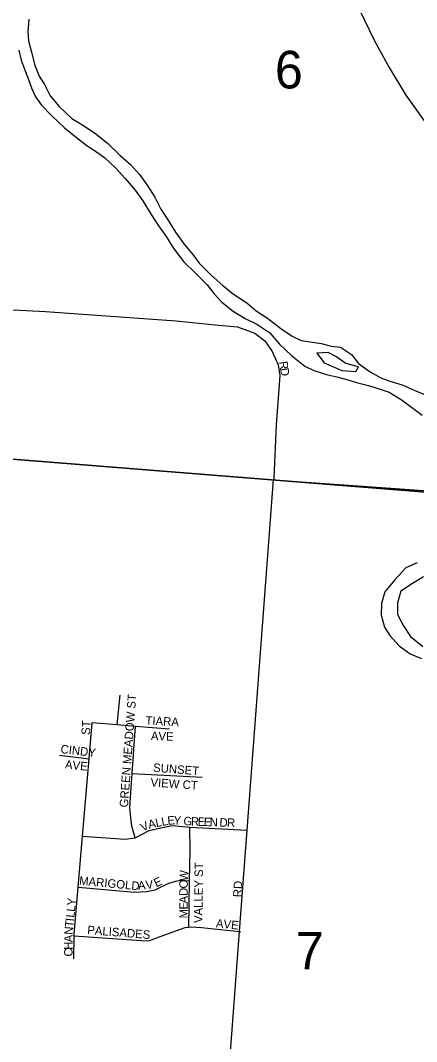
# Model space of a CAD drawing. Extents: x 0 to 34, y 0 to 22.
# Drawn here: x 4.316 to 4.758, y 16.625 to 17.763 of the extents above; entities that cross this region are included whole.
import ezdxf

# ---------------------------------------------------------------- set-up
doc = ezdxf.new("R2010")
doc.units = 0
for name, color, linetype in [('GM_X_City_Street', 7, 'Continuous'), ('GM_X_City_Street_Text', 7, 'Continuous'), ('GM_X_Major_River', 7, 'Continuous'), ('GM_X_Section', 7, 'Continuous'), ('GM_X_Section_Text', 7, 'Continuous'), ('GM_X_US_Route', 7, 'Continuous')]:
    doc.layers.add(name, color=color, linetype=linetype)

msp = doc.modelspace()

# ---------------------------------------------------------------- linework, layer by layer
at = {"layer": 'GM_X_City_Street'}
for points in [[(4.1861, 17.4467), (4.3444, 17.4382), (4.49, 17.4278), (4.5336, 17.4235), (4.5584, 17.4213), (4.5777, 17.4143), (4.589, 17.4057), (4.5971, 17.3939), (4.6036, 17.3788), (4.6057, 17.3669), (4.6014, 17.312), (4.5988, 17.2527)], [(4.5216, 16.2252), (4.5608, 16.7472), (4.5693, 16.8602), (4.5987, 17.2509)], [(4.5988, 17.2527), (4.5987, 17.2509), (4.8338, 17.234), (4.9075, 17.2287), (5.0472, 17.218), (5.1112, 17.2137), (5.1718, 17.2206), (5.2384, 17.2265), (5.2646, 17.2259), (5.2903, 17.2238), (5.3134, 17.2192), (5.3431, 17.2104), (5.3688, 17.2001), (5.3842, 17.1924), (5.3949, 17.1868), (5.44, 17.1631), (5.4728, 17.1515), (5.4951, 17.1479), (5.5183, 17.1487), (5.5352, 17.1515), (5.5507, 17.1555), (5.565, 17.1611), (5.578, 17.1683), (5.5851, 17.1734)], [(4.4243, 16.9779), (4.4276, 17.0106)], [(4.3759, 16.7167), (4.3761, 16.7426), (4.3761, 16.7445), (4.3806, 16.7966), (4.3856, 16.8535), (4.393, 16.9398), (4.3965, 16.9801)], [(4.3965, 16.9801), (4.4243, 16.9779), (4.4448, 16.9762), (4.4824, 16.9732)], [(4.4443, 16.8518), (4.4406, 16.8647), (4.4395, 16.8742), (4.4383, 16.8856), (4.4397, 16.9077), (4.4409, 16.9233), (4.4448, 16.9762)], [(4.3598, 16.9439), (4.393, 16.9398)], [(4.4409, 16.9233), (4.519, 16.9193)], [(4.3856, 16.8535), (4.4327, 16.8503), (4.4443, 16.8518), (4.46, 16.8599), (4.4729, 16.863), (4.4854, 16.8653), (4.5053, 16.8636), (4.5693, 16.8602)], [(4.504, 16.7522), (4.505, 16.8038), (4.5057, 16.8376), (4.5053, 16.8636)], [(4.3806, 16.7966), (4.4436, 16.7911), (4.4569, 16.7919), (4.4667, 16.7938), (4.4819, 16.8011), (4.491, 16.8037), (4.4955, 16.8045), (4.505, 16.8038)], [(4.3761, 16.7426), (4.4567, 16.7368), (4.4608, 16.7372), (4.4722, 16.7418), (4.4999, 16.7517), (4.504, 16.7522), (4.5067, 16.7525), (4.5181, 16.7518), (4.5608, 16.7472), (4.562, 16.7471)]]:
    msp.add_lwpolyline(points, dxfattribs=at)
at = {"layer": 'GM_X_Major_River'}
for points in [[(4.3257, 17.7641), (4.3245, 17.7501), (4.3253, 17.7402), (4.3287, 17.7273), (4.3325, 17.7129), (4.3374, 17.7008), (4.3431, 17.6913), (4.3495, 17.6788), (4.3594, 17.6667), (4.3737, 17.6534), (4.3866, 17.6458), (4.4006, 17.6363), (4.4139, 17.6257), (4.4271, 17.6128), (4.4392, 17.6022), (4.4491, 17.5909), (4.4578, 17.5791), (4.4661, 17.5658), (4.4729, 17.5526), (4.4813, 17.5393), (4.4892, 17.5268), (4.4987, 17.5139), (4.5085, 17.5018), (4.5157, 17.4923), (4.529, 17.479), (4.5422, 17.4673), (4.5539, 17.4578)], [(4.3147, 17.7296), (4.3173, 17.7186)], [(4.3173, 17.7186), (4.3215, 17.7068), (4.3253, 17.697), (4.3287, 17.6875), (4.3332, 17.6776), (4.3397, 17.6682), (4.3514, 17.6564), (4.3654, 17.6431), (4.3787, 17.6325), (4.3904, 17.6234), (4.4002, 17.617), (4.4101, 17.6102), (4.4226, 17.598), (4.4332, 17.5867), (4.4442, 17.5738), (4.4529, 17.5617), (4.462, 17.5465), (4.4703, 17.534), (4.479, 17.5218), (4.4866, 17.5093), (4.4983, 17.4942), (4.5119, 17.4809), (4.5244, 17.468), (4.5324, 17.4582), (4.5411, 17.4487), (4.5536, 17.4388), (4.5668, 17.4305), (4.5801, 17.4244), (4.5945, 17.4146), (4.6054, 17.4021), (4.6187, 17.3892), (4.6335, 17.3774), (4.6437, 17.3725), (4.6577, 17.3683), (4.6706, 17.3653), (4.6804, 17.3627), (4.691, 17.3593), (4.7043, 17.3559), (4.7175, 17.3517), (4.7277, 17.3483), (4.741, 17.3403), (4.7539, 17.3305), (4.7645, 17.3229)], [(4.5539, 17.4578), (4.5687, 17.4479), (4.5793, 17.4392), (4.5918, 17.4309), (4.6066, 17.4195), (4.6194, 17.4108), (4.6293, 17.4059), (4.6395, 17.4044), (4.652, 17.4029), (4.663, 17.3998), (4.6732, 17.3987), (4.6857, 17.3904), (4.6933, 17.3805), (4.7062, 17.371), (4.7183, 17.3646), (4.7281, 17.3608), (4.7421, 17.3566), (4.7554, 17.3506), (4.7671, 17.346)], [(4.6933, 17.3767), (4.6793, 17.3805), (4.6679, 17.3881), (4.6596, 17.3926), (4.6467, 17.3918)], [(4.6467, 17.3918), (4.655, 17.3812), (4.6747, 17.3725), (4.6902, 17.3714), (4.6933, 17.3767)], [(4.7587, 17.1583), (4.7462, 17.1526), (4.7337, 17.1393), (4.7228, 17.126), (4.719, 17.1131), (4.7186, 17.0999), (4.7224, 17.0866), (4.7284, 17.0771), (4.7387, 17.0658), (4.7511, 17.0567), (4.7636, 17.0517)], [(4.7659, 17.1428), (4.7534, 17.1352), (4.7406, 17.1268), (4.7368, 17.1135), (4.7368, 17.1006), (4.7436, 17.0881), (4.7515, 17.076), (4.7652, 17.065)]]:
    msp.add_lwpolyline(points, dxfattribs=at)
at = {"layer": 'GM_X_Section'}
for points in [[(4.2418, 18.2267), (4.7469, 18.1907), (5.1885, 18.1592), (5.123, 17.2087), (4.1767, 17.2841)], [(4.1767, 17.2841), (5.123, 17.2087), (5.0408, 16.1927), (4.1066, 16.2613), (4.1718, 17.2163)]]:
    msp.add_lwpolyline(points, close=True, dxfattribs=at)
at = {"layer": 'GM_X_US_Route'}
msp.add_lwpolyline([(4.6943, 17.7748), (4.7113, 17.7399), (4.7276, 17.7105), (4.7461, 17.6796), (4.7741, 17.6405), (4.8111, 17.5941), (4.8412, 17.5624), (4.8703, 17.5346), (4.9071, 17.5032), (4.9636, 17.4629), (5.0105, 17.4353), (5.0559, 17.4124), (5.093, 17.397), (5.1381, 17.3797), (5.3028, 17.3197), (5.444, 17.2679), (5.578, 17.2191), (5.6056, 17.2084)], dxfattribs=at)

# ---------------------------------------------------------------- texts
at = {"layer": 'GM_X_City_Street_Text'}
for s, rotation, p in [('R', 278.8994, (4.6047, 17.3822)), ('D', 278.226, (4.6059, 17.3748)), ('GREEN MEADOW ST', 85.7318, (4.4362, 16.8853)), ('ST', 86.4254, (4.3937, 16.9662)), ('TIARA', 357.27, (4.4556, 16.9779)), ('AVE', 358.0261, (4.4617, 16.9607)), ('CINDY', 353.5154, (4.3607, 16.9462)), ('AVE', 354.0969, (4.3657, 16.9291)), ('SUNSET', 355.5994, (4.464, 16.9254)), ('VIEW CT', 355.9842, (4.4611, 16.9091)), ('V', 25.0988, (4.4528, 16.8584)), ('A', 13.4107, (4.4598, 16.8617)), ('L', 10.6885, (4.4678, 16.8636)), ('L', 10.7131, (4.4744, 16.8649)), ('E', 5.3626, (4.4807, 16.8661)), ('Y', 356.6977, (4.4869, 16.8667)), ('G', 355.8157, (4.4978, 16.866)), ('R', 357.7837, (4.5064, 16.8654)), ('E', 358.2096, (4.514, 16.8651)), ('E', 358.1964, (4.5207, 16.8649)), ('N', 358.2026, (4.5273, 16.8647)), ('D', 358.2074, (4.5382, 16.8643)), ('R', 358.188, (4.5465, 16.8641)), ('VALLEY ST', 89.2365, (4.5192, 16.7567)), ('W', 86.5013, (4.503, 16.8034)), ('MARIGOLD', 354.6676, (4.3815, 16.7995)), ('A', 5.5388, (4.4478, 16.7937)), ('V', 7.8839, (4.4566, 16.7945)), ('E', 24.5582, (4.4677, 16.7965)), ('O', 89.4316, (4.5029, 16.7952)), ('RD', 86.9884, (4.5629, 16.7853)), ('D', 89.9703, (4.5029, 16.7869)), ('Y', 84.1763, (4.3777, 16.7757)), ('A', 89.9703, (4.5029, 16.7786)), ('E', 89.9707, (4.5029, 16.7719)), ('L', 84.173, (4.3764, 16.7624)), ('L', 84.1977, (4.377, 16.769)), ('M', 89.9636, (4.5029, 16.7619)), ('T', 84.2269, (4.3753, 16.7516)), ('I', 84.1763, (4.3759, 16.7583)), ('AVE', 354.0895, (4.534, 16.752)), ('A', 89.3879, (4.3746, 16.7352)), ('N', 85.603, (4.3746, 16.7434)), ('PALISADES', 355.4257, (4.3906, 16.7445)), ('H', 89.9362, (4.3745, 16.7269)), ('C', 89.9271, (4.3745, 16.7194))]:
    msp.add_text(s, height=0.00947, rotation=rotation, dxfattribs=at).set_placement(p)
at = {"layer": 'GM_X_Section_Text'}
for s, p in [('6', (4.6001, 17.687)), ('7', (4.6234, 16.705))]:
    msp.add_text(s, height=0.0419, rotation=0, dxfattribs=at).set_placement(p)

doc.saveas('drawing.dxf')
